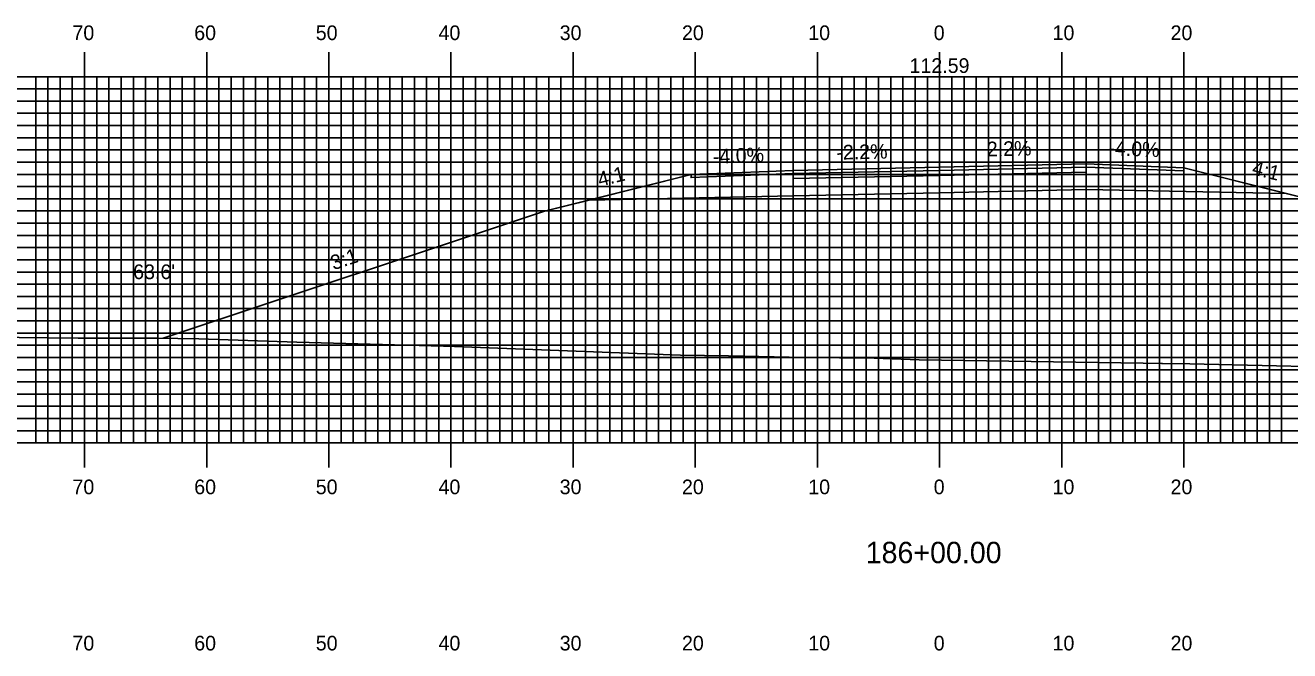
# Model space of a CAD drawing. Extents: x 1787369 to 1787713, y 442591 to 442811.
# Drawn here: x 1787460.2 to 1787563.8, y 442646.6 to 442697.9 of the extents above; entities that cross this region are included whole.
import ezdxf

# ---------------------------------------------------------------- set-up
doc = ezdxf.new("R2010")
doc.units = 0
for name, color, linetype in [('ANNOTATION', 7, 'Continuous'), ('D_Roadway_Centerline', 7, 'Continuous'), ('D_Roadway_Centerline_Text', 7, 'Continuous'), ('D_Roadway_Edge_Shoulder', 7, 'Continuous'), ('D_Roadway_Edge_TW', 7, 'Continuous'), ('D_Roadway_Pavement', 7, 'Continuous'), ('D_Roadway_SlopeLines', 7, 'Continuous'), ('D_Roadway_SubGrade', 7, 'Continuous'), ('D_Text_Standard', 7, 'Continuous'), ('H_V ANNOTATION', 7, 'Continuous'), ('MAJOR', 7, 'Continuous'), ('MINOR', 7, 'Continuous'), ('S_Roadway_Centerline', 7, 'Continuous')]:
    doc.layers.add(name, color=color, linetype=linetype)

msp = doc.modelspace()

# ---------------------------------------------------------------- linework, layer by layer
at = {"layer": 'D_Roadway_Centerline'}
msp.add_lwpolyline([(1787471.54, 442672.25), (1787502.75, 442682.65), (1787506.42, 442683.57), (1787514.75, 442685.65), (1787523.1, 442685.99), (1787535.1, 442686.25), (1787547.1, 442686.52), (1787555.1, 442686.2), (1787563.47, 442684.11), (1787567.1, 442683.2), (1787606.38, 442670.11)], dxfattribs=at)
at = {"layer": 'D_Roadway_Edge_Shoulder'}
for points in [[(1787547.1, 442686.52), (1787555.1, 442686.2), (1787555.1, 442685.95), (1787547.1, 442686.27)], [(1787523.1, 442685.99), (1787514.75, 442685.65), (1787514.75, 442685.4), (1787523.1, 442685.74)]]:
    msp.add_lwpolyline(points, close=True, dxfattribs=at)
at = {"layer": 'D_Roadway_Edge_TW'}
msp.add_lwpolyline([(1787523.1, 442685.74), (1787523.1, 442685.99), (1787535.1, 442686.25), (1787547.1, 442686.52), (1787547.1, 442686.27), (1787535.1, 442686)], close=True, dxfattribs=at)
at = {"layer": 'D_Roadway_Pavement'}
msp.add_lwpolyline([(1787523.1, 442685.32), (1787523.1, 442685.74), (1787535.1, 442686), (1787547.1, 442686.27), (1787547.1, 442685.85), (1787535.1, 442685.59)], close=True, dxfattribs=at)
at = {"layer": 'D_Roadway_SlopeLines'}
for points in [[(1787514.75, 442685.65), (1787502.75, 442682.65), (1787471.54, 442672.25)], [(1787555.1, 442686.2), (1787567.1, 442683.2), (1787606.38, 442670.11)]]:
    msp.add_lwpolyline(points, dxfattribs=at)
at = {"layer": 'D_Roadway_SubGrade'}
msp.add_lwpolyline([(1787523.1, 442683.91), (1787506.42, 442683.57), (1787514.75, 442685.65), (1787514.75, 442685.4), (1787523.1, 442685.74), (1787535.1, 442686), (1787547.1, 442686.27), (1787555.1, 442685.95), (1787555.1, 442686.2), (1787563.47, 442684.11), (1787547.1, 442684.43), (1787535.1, 442684.17)], close=True, dxfattribs=at)
at = {"layer": 'MAJOR'}
for p, q in [((1787465.1, 442695.67), (1787465.1, 442693.67)), ((1787475.1, 442695.67), (1787475.1, 442693.67)), ((1787485.1, 442695.67), (1787485.1, 442693.67)), ((1787495.1, 442695.67), (1787495.1, 442693.67)), ((1787505.1, 442695.67), (1787505.1, 442693.67)), ((1787515.1, 442695.67), (1787515.1, 442693.67)), ((1787525.1, 442695.67), (1787525.1, 442693.67)), ((1787535.1, 442695.67), (1787535.1, 442693.67)), ((1787545.1, 442695.67), (1787545.1, 442693.67)), ((1787555.1, 442695.67), (1787555.1, 442693.67)), ((1787395.1, 442693.67), (1787675.1, 442693.67)), ((1787395.1, 442693.67), (1787675.1, 442693.67)), ((1787465.1, 442663.67), (1787465.1, 442693.67)), ((1787475.1, 442663.67), (1787475.1, 442693.67)), ((1787485.1, 442663.67), (1787485.1, 442693.67)), ((1787495.1, 442663.67), (1787495.1, 442693.67)), ((1787505.1, 442663.67), (1787505.1, 442693.67)), ((1787515.1, 442663.67), (1787515.1, 442693.67)), ((1787525.1, 442663.67), (1787525.1, 442693.67)), ((1787535.1, 442663.67), (1787535.1, 442693.67)), ((1787545.1, 442663.67), (1787545.1, 442693.67)), ((1787555.1, 442663.67), (1787555.1, 442693.67)), ((1787395.1, 442688.67), (1787675.1, 442688.67)), ((1787395.1, 442683.67), (1787675.1, 442683.67)), ((1787395.1, 442678.67), (1787675.1, 442678.67)), ((1787395.1, 442673.67), (1787675.1, 442673.67)), ((1787395.1, 442668.67), (1787675.1, 442668.67)), ((1787395.1, 442663.67), (1787675.1, 442663.67)), ((1787395.1, 442663.67), (1787675.1, 442663.67)), ((1787465.1, 442661.66), (1787465.1, 442663.67)), ((1787475.1, 442661.66), (1787475.1, 442663.67)), ((1787485.1, 442661.66), (1787485.1, 442663.67)), ((1787495.1, 442661.66), (1787495.1, 442663.67)), ((1787505.1, 442661.66), (1787505.1, 442663.67)), ((1787515.1, 442661.66), (1787515.1, 442663.67)), ((1787525.1, 442661.66), (1787525.1, 442663.67)), ((1787535.1, 442661.66), (1787535.1, 442663.67)), ((1787545.1, 442661.66), (1787545.1, 442663.67)), ((1787555.1, 442661.66), (1787555.1, 442663.67))]:
    msp.add_line(p, q, dxfattribs=at)
at = {"layer": 'MINOR'}
for p, q in [((1787461.1, 442663.67), (1787461.1, 442693.67)), ((1787462.1, 442663.67), (1787462.1, 442693.67)), ((1787463.1, 442663.67), (1787463.1, 442693.67)), ((1787464.1, 442663.67), (1787464.1, 442693.67)), ((1787466.1, 442663.67), (1787466.1, 442693.67)), ((1787467.1, 442663.67), (1787467.1, 442693.67)), ((1787468.1, 442663.67), (1787468.1, 442693.67)), ((1787469.1, 442663.67), (1787469.1, 442693.67)), ((1787470.1, 442663.67), (1787470.1, 442693.67)), ((1787471.1, 442663.67), (1787471.1, 442693.67)), ((1787472.1, 442663.67), (1787472.1, 442693.67)), ((1787473.1, 442663.67), (1787473.1, 442693.67)), ((1787474.1, 442663.67), (1787474.1, 442693.67)), ((1787476.1, 442663.67), (1787476.1, 442693.67)), ((1787477.1, 442663.67), (1787477.1, 442693.67)), ((1787478.1, 442663.67), (1787478.1, 442693.67)), ((1787479.1, 442663.67), (1787479.1, 442693.67)), ((1787480.1, 442663.67), (1787480.1, 442693.67)), ((1787481.1, 442663.67), (1787481.1, 442693.67)), ((1787482.1, 442663.67), (1787482.1, 442693.67)), ((1787483.1, 442663.67), (1787483.1, 442693.67)), ((1787484.1, 442663.67), (1787484.1, 442693.67)), ((1787486.1, 442663.67), (1787486.1, 442693.67)), ((1787487.1, 442663.67), (1787487.1, 442693.67)), ((1787488.1, 442663.67), (1787488.1, 442693.67)), ((1787489.1, 442663.67), (1787489.1, 442693.67)), ((1787490.1, 442663.67), (1787490.1, 442693.67)), ((1787491.1, 442663.67), (1787491.1, 442693.67)), ((1787492.1, 442663.67), (1787492.1, 442693.67)), ((1787493.1, 442663.67), (1787493.1, 442693.67)), ((1787494.1, 442663.67), (1787494.1, 442693.67)), ((1787496.1, 442663.67), (1787496.1, 442693.67)), ((1787497.1, 442663.67), (1787497.1, 442693.67)), ((1787498.1, 442663.67), (1787498.1, 442693.67)), ((1787499.1, 442663.67), (1787499.1, 442693.67)), ((1787500.1, 442663.67), (1787500.1, 442693.67)), ((1787501.1, 442663.67), (1787501.1, 442693.67)), ((1787502.1, 442663.67), (1787502.1, 442693.67)), ((1787503.1, 442663.67), (1787503.1, 442693.67)), ((1787504.1, 442663.67), (1787504.1, 442693.67)), ((1787506.1, 442663.67), (1787506.1, 442693.67)), ((1787507.1, 442663.67), (1787507.1, 442693.67)), ((1787508.1, 442663.67), (1787508.1, 442693.67)), ((1787509.1, 442663.67), (1787509.1, 442693.67)), ((1787510.1, 442663.67), (1787510.1, 442693.67)), ((1787511.1, 442663.67), (1787511.1, 442693.67)), ((1787512.1, 442663.67), (1787512.1, 442693.67)), ((1787513.1, 442663.67), (1787513.1, 442693.67)), ((1787514.1, 442663.67), (1787514.1, 442693.67)), ((1787516.1, 442663.67), (1787516.1, 442693.67)), ((1787517.1, 442663.67), (1787517.1, 442693.67)), ((1787518.1, 442663.67), (1787518.1, 442693.67)), ((1787519.1, 442663.67), (1787519.1, 442693.67)), ((1787520.1, 442663.67), (1787520.1, 442693.67)), ((1787521.1, 442663.67), (1787521.1, 442693.67)), ((1787522.1, 442663.67), (1787522.1, 442693.67)), ((1787523.1, 442663.67), (1787523.1, 442693.67)), ((1787524.1, 442663.67), (1787524.1, 442693.67)), ((1787526.1, 442663.67), (1787526.1, 442693.67)), ((1787527.1, 442663.67), (1787527.1, 442693.67)), ((1787528.1, 442663.67), (1787528.1, 442693.67)), ((1787529.1, 442663.67), (1787529.1, 442693.67)), ((1787530.1, 442663.67), (1787530.1, 442693.67)), ((1787531.1, 442663.67), (1787531.1, 442693.67)), ((1787532.1, 442663.67), (1787532.1, 442693.67)), ((1787533.1, 442663.67), (1787533.1, 442693.67)), ((1787534.1, 442663.67), (1787534.1, 442693.67)), ((1787536.1, 442663.67), (1787536.1, 442693.67)), ((1787537.1, 442663.67), (1787537.1, 442693.67)), ((1787538.1, 442663.67), (1787538.1, 442693.67)), ((1787539.1, 442663.67), (1787539.1, 442693.67)), ((1787540.1, 442663.67), (1787540.1, 442693.67)), ((1787541.1, 442663.67), (1787541.1, 442693.67)), ((1787542.1, 442663.67), (1787542.1, 442693.67)), ((1787543.1, 442663.67), (1787543.1, 442693.67)), ((1787544.1, 442663.67), (1787544.1, 442693.67)), ((1787546.1, 442663.67), (1787546.1, 442693.67)), ((1787547.1, 442663.67), (1787547.1, 442693.67)), ((1787548.1, 442663.67), (1787548.1, 442693.67)), ((1787549.1, 442663.67), (1787549.1, 442693.67)), ((1787550.1, 442663.67), (1787550.1, 442693.67)), ((1787551.1, 442663.67), (1787551.1, 442693.67)), ((1787552.1, 442663.67), (1787552.1, 442693.67)), ((1787553.1, 442663.67), (1787553.1, 442693.67)), ((1787554.1, 442663.67), (1787554.1, 442693.67)), ((1787556.1, 442663.67), (1787556.1, 442693.67)), ((1787557.1, 442663.67), (1787557.1, 442693.67)), ((1787558.1, 442663.67), (1787558.1, 442693.67)), ((1787559.1, 442663.67), (1787559.1, 442693.67)), ((1787560.1, 442663.67), (1787560.1, 442693.67)), ((1787561.1, 442663.67), (1787561.1, 442693.67)), ((1787562.1, 442663.67), (1787562.1, 442693.67)), ((1787563.1, 442663.67), (1787563.1, 442693.67)), ((1787395.1, 442692.67), (1787675.1, 442692.67)), ((1787395.1, 442691.67), (1787675.1, 442691.67)), ((1787395.1, 442690.67), (1787675.1, 442690.67)), ((1787395.1, 442689.67), (1787675.1, 442689.67)), ((1787395.1, 442687.67), (1787675.1, 442687.67)), ((1787395.1, 442686.67), (1787675.1, 442686.67)), ((1787395.1, 442685.67), (1787675.1, 442685.67)), ((1787395.1, 442684.67), (1787675.1, 442684.67)), ((1787395.1, 442682.67), (1787675.1, 442682.67)), ((1787395.1, 442681.67), (1787675.1, 442681.67)), ((1787395.1, 442680.67), (1787675.1, 442680.67)), ((1787395.1, 442679.67), (1787675.1, 442679.67)), ((1787395.1, 442677.67), (1787675.1, 442677.67)), ((1787395.1, 442676.67), (1787675.1, 442676.67)), ((1787395.1, 442675.67), (1787675.1, 442675.67)), ((1787395.1, 442674.67), (1787675.1, 442674.67)), ((1787395.1, 442672.67), (1787675.1, 442672.67)), ((1787395.1, 442671.67), (1787675.1, 442671.67)), ((1787395.1, 442670.67), (1787675.1, 442670.67)), ((1787395.1, 442669.67), (1787675.1, 442669.67)), ((1787395.1, 442667.67), (1787675.1, 442667.67)), ((1787395.1, 442666.67), (1787675.1, 442666.67)), ((1787395.1, 442665.67), (1787675.1, 442665.67)), ((1787395.1, 442664.67), (1787675.1, 442664.67))]:
    msp.add_line(p, q, dxfattribs=at)
at = {"layer": 'S_Roadway_Centerline'}
msp.add_lwpolyline([(1787454.88, 442672.35), (1787464.57, 442672.24), (1787471.02, 442672.26), (1787474.45, 442672.2), (1787482.48, 442671.93), (1787494.48, 442671.61), (1787494.68, 442671.6), (1787513.88, 442670.86), (1787517.82, 442670.8), (1787524.05, 442670.68), (1787529.74, 442670.6), (1787533.43, 442670.49), (1787551.78, 442670.21), (1787553.26, 442670.18), (1787553.34, 442670.18), (1787555.6, 442670.14), (1787572.15, 442669.78)], dxfattribs=at)

# ---------------------------------------------------------------- texts
at = {"layer": 'ANNOTATION'}
for s, rotation, p in [('-4.0%', 2.2906, (1787516.56, 442686.53)), ('-2.2%', 1.2603, (1787526.66, 442686.87)), ('2.2%', 1.2603, (1787538.98, 442687.14)), ('-4.0%', 357.7094, (1787548.9, 442687.25)), ('4:1', 345.9638, (1787560.61, 442685.68)), ('4:1', 14.0362, (1787507.28, 442684.65)), ('3:1', 18.4348, (1787485.48, 442677.81))]:
    msp.add_text(s, height=1.2, rotation=rotation, dxfattribs=at).set_placement(p)
at = {"layer": 'D_Roadway_Centerline'}
for s in ['C', 'L']:
    msp.add_text(s, height=0.0146, dxfattribs=at).set_placement((1787535.1, 442686.25))
at = {"layer": 'D_Roadway_Centerline_Text'}
msp.add_text('112.59', height=1.2, dxfattribs=at).set_placement((1787532.64, 442693.98))
at = {"layer": 'D_Text_Standard'}
msp.add_text("63.6'", height=1.2, dxfattribs=at).set_placement((1787469.08, 442677.09))
at = {"layer": 'H_V ANNOTATION'}
for s, height, p in [('70', 1.2, (1787464.11, 442696.67)), ('60', 1.2, (1787474.08, 442696.67)), ('50', 1.2, (1787484.03, 442696.67)), ('40', 1.2, (1787494.08, 442696.67)), ('30', 1.2, (1787504, 442696.67)), ('20', 1.2, (1787514.01, 442696.67)), ('10', 1.2, (1787524.35, 442696.67)), ('0', 1.2, (1787534.62, 442696.67)), ('10', 1.2, (1787544.35, 442696.67)), ('20', 1.2, (1787554.01, 442696.67)), ('70', 1.2, (1787464.11, 442659.47)), ('60', 1.2, (1787474.08, 442659.47)), ('50', 1.2, (1787484.03, 442659.47)), ('40', 1.2, (1787494.08, 442659.47)), ('30', 1.2, (1787504, 442659.47)), ('20', 1.2, (1787514.01, 442659.47)), ('10', 1.2, (1787524.35, 442659.47)), ('0', 1.2, (1787534.62, 442659.47)), ('10', 1.2, (1787544.35, 442659.47)), ('20', 1.2, (1787554.01, 442659.47)), ('186+00.00', 1.75, (1787529.05, 442653.82)), ('70', 1.2, (1787464.11, 442646.67)), ('60', 1.2, (1787474.08, 442646.67)), ('50', 1.2, (1787484.03, 442646.67)), ('40', 1.2, (1787494.08, 442646.67)), ('30', 1.2, (1787504, 442646.67)), ('20', 1.2, (1787514.01, 442646.67)), ('10', 1.2, (1787524.35, 442646.67)), ('0', 1.2, (1787534.62, 442646.67)), ('10', 1.2, (1787544.35, 442646.67)), ('20', 1.2, (1787554.01, 442646.67))]:
    msp.add_text(s, height=height, dxfattribs=at).set_placement(p)

doc.saveas('drawing.dxf')
